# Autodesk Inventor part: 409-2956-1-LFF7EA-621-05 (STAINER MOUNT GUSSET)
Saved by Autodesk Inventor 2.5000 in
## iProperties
Created: 2010-06
Part Number: 409-2956-1-LFF7EA-621-05 (STAINER MOUNT GUSSET)
Cost Center: 0 lbmass
Material: A36 STEEL PLATE
Document SubType Name: Sheet Metal
Designer: S. Boerckel
Authority: 0 in^3
Mass: 347.163 g
Surface Area: 121.255 cm^2
Volume: 44.1683 cm^3
Density: 7.86 g/cm^3
Flat Pattern Width: 6.35 cm
Flat Pattern Length: 10.4775 cm
Flat Pattern Area: 66.5321 cm^2
Sheet Metal Rule: 3/8"Thk
Sheet Metal Width: 4.1250 in
Sheet Metal Length: 10.3125 in^2
Description: STRAINER MOUNT GUSSET
User Status: BURN
SaveDate: 2008-01-15
SaveTime: 10:24
FileName: Sheet Metal
Wide: =<Flat Pattern Width>cm
Length: =<Flat Pattern Length>cm
Thickness: 0.3750 in
SMR: =<Sheet Metal Rule> - <Material>
Author: S. Boerckel
Revision Number: 0
Subject: DEMIN WATER FORWARDING PUMP SKID-7EA
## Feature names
1. Plate1
2. Cut1
